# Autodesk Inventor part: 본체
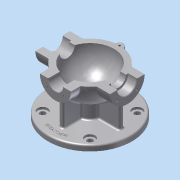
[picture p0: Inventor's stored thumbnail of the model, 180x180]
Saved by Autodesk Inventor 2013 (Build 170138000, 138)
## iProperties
Created: 2015-12
Part Number: 본체
Material: 알루미늄 6061
Document SubType Name: Modeling
Designer: mduedu
Density: 1 g/cm^3
Mass: 407.074 g
Surface Area: 905.391 cm^2
Volume: 407.074 cm^3
Author: mduedu
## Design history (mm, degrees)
sketch "스케치1"
  geometry: L1 (-53, 0)-(53, 0); A1 r 53 centre (0, 0) between (53, 0) and (-53, 0); 2 further points
  constraints: 2 coincident, 2 end point, 2 point on circle, 1 centre point, 1 horizontal, 1 midpoint
  dimensions: "d0" = 53 radius of A1
revolve "회전1" sketch "스케치1" stored, may be unused: angle "d2" = 90 deg
feature "쉘1" dims "d11" = 10
node "작업 평면1"
sketch "스케치2"
  geometry: C1 r 31 at (0, 0); 1 further point
  constraints: 1 centre point, 1 coincident
  dimensions: "d4" = 62 diameter of C1
extrude "돌출1" join sketch "스케치2" stored distance "d5" = 10; taper "d6" = 0 deg
node "작업 평면2"
sketch "스케치3"
  geometry: C1 r 28 at (0, 0); 1 further point
  constraints: 1 centre point, 1 coincident
  dimensions: "d8" = 56 diameter of C1
extrude "돌출2" join sketch "스케치3" stored distance "d9" = 10; taper "d10" = 0 deg
hole "구멍1" diameter "d14" = 35; stored, may be unused: countersink angle "d18" = 90 deg, drill point angle "d20" = 0 deg; dims "d12" = 10, "d13" = 10, "d15" = 6, "d16" = 4, "d17" = 2, "d19" = 16
hole "구멍2" diameter "d23" = 27; stored, may be unused: countersink angle "d27" = 90 deg, drill point angle "d29" = 0 deg; dims "d21" = 10, "d22" = 10, "d24" = 6, "d25" = 4, "d26" = 2, "d28" = 16
fillet "모깎기1" dims "d30" = 0.3
hole "구멍3" diameter "d33" = 26; stored, may be unused: countersink angle "d37" = 90 deg, drill point angle "d39" = 0 deg; dims "d31" = 10, "d32" = 10, "d34" = 6, "d35" = 4, "d36" = 2, "d38" = 16
chamfer "모따기1" distance "d40" = 1; stored, may be unused: second distance "d41" = 2, angle "d42" = 45 deg
sketch "스케치4"
  geometry: L1 (0, 0)-(0, -25); L2 (0, 0)-(-17.678, -17.678); A1 r 25 centre (0, 0) between (-17.678, -17.678) and (0, -25); 1 further point
  constraints: 4 end point, 2 point on circle, 1 centre point, 1 coincident, 1 vertical
  dimensions: "d43" = 50 diameter of A1; "d47" = 45 deg angle of L1 L2
hole "구멍4" sketch "스케치4" at (-17.678, -17.678) diameter "d49" = 3.242; stored, may be unused: countersink angle "d53" = 90 deg, drill point angle "d55" = 118 deg; dims "d50" = 11, "d51" = 4, "d52" = 2, "d54" = 13
sketch "스케치5"
  geometry: L1 (0, 0)-(0, -20); L2 (0, 0)-(-14.142, -14.142); A1 r 20 centre (0, 0) between (0, -20) and (-14.142, -14.142); 2 further points
  constraints: 4 end point, 2 coincident, 2 point on circle, 1 centre point, 1 vertical
  dimensions: "d59" = 40 diameter of A1; "d65" = 45 deg angle of L1 L2
hole "구멍5" sketch "스케치5" at (-14.142, -14.142) diameter "d67" = 3.242; stored, may be unused: countersink angle "d71" = 90 deg, drill point angle "d73" = 118 deg; dims "d68" = 8, "d69" = 4, "d70" = 2, "d72" = 10
node "작업 평면3"
sketch "스케치6"
  geometry: C1 r 75 at (0, 0); 1 further point
  constraints: 1 centre point, 1 coincident
  dimensions: "d78" = 150 diameter of C1
extrude "돌출3" join sketch "스케치6" distance "d80" = 10; taper "d81" = 0 deg
sketch "스케치7"
  geometry: C1 r 20 at (0, 0); 1 further point
  constraints: 1 centre point, 1 coincident
  dimensions: "d82" = 40 diameter of C1
extrude "돌출4" join sketch "스케치7" stored distance "d84" = 10; taper "d85" = 0 deg
sketch "스케치8"
  geometry: 2 further points
  constraints: 1 coincident
hole "구멍6" sketch "스케치8" at (0, 0) diameter "d86" = 20; stored, may be unused: countersink angle "d90" = 90 deg, drill point angle "d92" = 118 deg; dims "d87" = 7, "d88" = 40, "d89" = 5, "d91" = 10
fillet "모깎기2" dims "d93" = 0.3
sketch "스케치9"
  geometry: L1 (-67, -18.5)-(-66, -17.5) reference; L2 (-66, -17.5)-(-51.3, -17.5) reference; L3 (-51, -17.2)-(-51, -13.5) reference; L4 (-51, -13.5)-(-40.826, -13.5) reference; L5 (-10, -41.821)-(-10, -80) reference; L6 (-10, -80)-(-19.7, -80) reference; L7 (-20, -80.3)-(-20, -85) reference; L8 (-20, -85)-(-75, -85) reference; L9 (-75, -85)-(-75, -75) reference; L10 (-75, -75)-(-20, -75) reference; L11 (-20, -75)-(-20, -49.082) reference; L12 (-42.988, -31)-(-67, -31) reference; L13 (-67, -31)-(-67, -18.5) reference; L14 (66, -17.5)-(67, -18.5) reference; L15 (67, -18.5)-(67, -31) reference; L16 (67, -31)-(42.988, -31) reference; L17 (20, -49.082)-(20, -75) reference; L18 (20, -75)-(75, -75) reference; L19 (75, -75)-(75, -85) reference; L20 (75, -85)-(20, -85) reference; L21 (20, -85)-(20, -80.3) reference; L22 (19.7, -80)-(10, -80) reference; L23 (10, -80)-(10, -41.821) reference; L24 (40.826, -13.5)-(51, -13.5) reference; L25 (51, -13.5)-(51, -17.2) reference; L26 (51.3, -17.5)-(66, -17.5) reference; L27 (67, 18.5)-(66, 17.5) reference; L28 (66, 17.5)-(51.3, 17.5) reference; L29 (51, 17.2)-(51, 13.5) reference; L30 (51, 13.5)-(40.826, 13.5) reference; L31 (-40.826, 13.5)-(-51, 13.5) reference; L32 (-51, 13.5)-(-51, 17.2) reference; L33 (-51.3, 17.5)-(-66, 17.5) reference; L34 (-66, 17.5)-(-67, 18.5) reference; L35 (-67, 18.5)-(-67, 31) reference; L36 (-67, 31)-(-42.988, 31) reference; L37 (42.988, 31)-(67, 31) reference; L38 (67, 31)-(67, 18.5) reference; L39 (-57, -31)-(-57, -75); A1 r 0.3 centre (-51.3, -17.2) between (-51.3, -17.5) and (-51, -17.2) reference; A2 r 43 centre (0, 0) between (-40.826, -13.5) and (-10, -41.821) reference; A3 r 0.3 centre (-19.7, -80.3) between (-19.7, -80) and (-20, -80.3) reference; A4 r 53 centre (0, 0) between (-42.988, -31) and (-20, -49.082) reference; A5 r 53 centre (0, 0) between (20, -49.082) and (42.988, -31) reference; A6 r 0.3 centre (19.7, -80.3) between (20, -80.3) and (19.7, -80) reference; A7 r 43 centre (0, 0) between (10, -41.821) and (40.826, -13.5) reference; A8 r 0.3 centre (51.3, -17.2) between (51, -17.2) and (51.3, -17.5) reference; A9 r 0.3 centre (51.3, 17.2) between (51.3, 17.5) and (51, 17.2) reference; A10 r 43 centre (0, 0) between (40.826, 13.5) and (-40.826, 13.5) reference; A11 r 0.3 centre (-51.3, 17.2) between (-51, 17.2) and (-51.3, 17.5) reference; A12 r 53 centre (0, 0) between (42.988, 31) and (-42.988, 31) reference; 1 further point
  constraints: 2 end point, 2 point on line, 1 perpendicular
  dimensions: "d151" = 10 distance between parallel lines of L39 L13
feature "리브1" sketch "스케치9" dims "d96" = 1, "d97" = 8, "d98" = 0, "d99" = 0, "d100" = 1, "d101" = 1
sketch "스케치14"
  geometry: L1 (-14, 62)-(-13, 61) reference; L2 (-13, 61)-(-13, 40.988) reference; L3 (-41.821, 10)-(-80, 10) reference; L4 (-80, 10)-(-80, 19.7) reference; L5 (-80.3, 20)-(-85, 20) reference; L6 (-85, 20)-(-85, 75) reference; L7 (-85, 75)-(-75, 75) reference; L8 (-75, 75)-(-75, 20) reference; L9 (-75, 20)-(-49.082, 20) reference; L10 (-28, 45)-(-28, 62) reference; L11 (-28, 62)-(-14, 62) reference; L12 (13, 61)-(14, 62) reference; L13 (14, 62)-(28, 62) reference; L14 (28, 62)-(28, 45) reference; L15 (-49.082, -20)-(-75, -20) reference; L16 (-75, -20)-(-75, -75) reference; L17 (-75, -75)-(-85, -75) reference; L18 (-85, -75)-(-85, -20) reference; L19 (-85, -20)-(-80.3, -20) reference; L20 (-80, -19.7)-(-80, -10) reference; L21 (-80, -10)-(-41.821, -10) reference; L22 (13, 40.988)-(13, 61) reference; L23 (-28, 52)-(-75, 52); A1 r 43 centre (0, 0) between (-13, 40.988) and (-41.821, 10) reference; A2 r 0.3 centre (-80.3, 19.7) between (-80, 19.7) and (-80.3, 20) reference; A3 r 53 centre (0, 0) between (-28, 45) and (-49.082, 20) reference; A4 r 53 centre (0, 0) between (0, -53) and (28, 45) reference; A5 r 53 centre (0, 0) between (-49.082, -20) and (0, -53) reference; A6 r 0.3 centre (-80.3, -19.7) between (-80.3, -20) and (-80, -19.7) reference; A7 r 43 centre (0, 0) between (-41.821, -10) and (0, -43) reference; A8 r 43 centre (0, 0) between (0, -43) and (13, 40.988) reference; 1 further point
  constraints: 2 end point, 2 point on line, 1 perpendicular
  dimensions: "d152" = 10 distance between parallel lines of L23 L11
feature "리브2" sketch "스케치14" dims "d153" = 1, "d154" = 8, "d155" = 0, "d156" = 0, "d157" = 1, "d158" = 1
sketch "스케치10"
  geometry: L1 (0, 0)-(0, -60); L2 (0, 0)-(-42.426, -42.426); A1 r 60 centre (0, 0) between (0, -60) and (-42.426, -42.426); 2 further points
  constraints: 4 end point, 2 coincident, 2 point on circle, 1 centre point, 1 vertical
  dimensions: "d105" = 120 diameter of A1; "d107" = 45 deg angle of L1 L2
hole "구멍7" sketch "스케치10" at (-42.426, -42.426) diameter "d109" = 10; stored, may be unused: countersink angle "d113" = 90 deg, drill point angle "d115" = 118 deg; dims "d110" = 7, "d111" = 18, "d112" = 4, "d114" = 10
fillet "모깎기3" dims "d120" = 3
fillet "모깎기4" dims "d121" = 3, "d122" = 3
fillet "모깎기5" dims "d123" = 3
fillet "모깎기6" dims "d124" = 3
sketch "스케치11"
  geometry: C1 r 75 at (0, 0) reference; C2 r 65 at (0, 0)
  constraints: 1 centre point, 1 coincident, 1 other
  dimensions: "d161" = 130 diameter of C2
feature "엠보싱1" sketch "스케치11" dims "d11" = 10, "d125" = 0.5, "d126" = 0
sketch "스케치12"
  geometry: L1 (0, 100)-(0, -100); L2 (0, 100)-(100, 100); L3 (100, 100)-(100, -100); L4 (100, -100)-(0, -100); 2 further points
  constraints: 8 end point, 3 perpendicular, 1 coincident, 1 midpoint, 1 vertical
  dimensions: "d127" = 200 distance of L2.end L3.end; "d129" = 100 distance between parallel lines of L1 L3
extrude "돌출5" cut sketch "스케치12" stored distance "d130" = 10; taper "d131" = 0 deg
sketch "스케치13"
  geometry: C1 r 7 at (0, 53); A1 r 53 centre (0, 0) between (42.113, 32.179) and (-42.113, 32.179) reference; 1 further point
  constraints: 1 centre point, 1 point on circle
  dimensions: "d132" = 14 diameter of C1
extrude "돌출6" join sketch "스케치13" distance "d134" = 15; taper "d135" = 0 deg
hole "구멍8" diameter "d139" = 3.242; stored, may be unused: countersink angle "d143" = 90 deg, drill point angle "d145" = 118 deg; dims "d140" = 8, "d141" = 4, "d142" = 2, "d144" = 10, "d148" = 10, "d149" = 10
fillet "모깎기7" dims "d146" = 3
fillet "모깎기8" dims "d147" = 3
node "솔리드1"
mirror "대칭1"
mirror "대칭2"
pattern_circular "원형 패턴1" dims angle "d57" = 360 deg
mirror "대칭3"
pattern_circular "원형 패턴2" dims angle "d75" = 360 deg
mirror "대칭4"
pattern_circular "원형 패턴4" dims angle "d118" = 360 deg
node "절단 모서리 투영1"
node "절단 모서리 투영2"
other parameters: "d3" = 67, "d7" = 62, "d77" = -85
